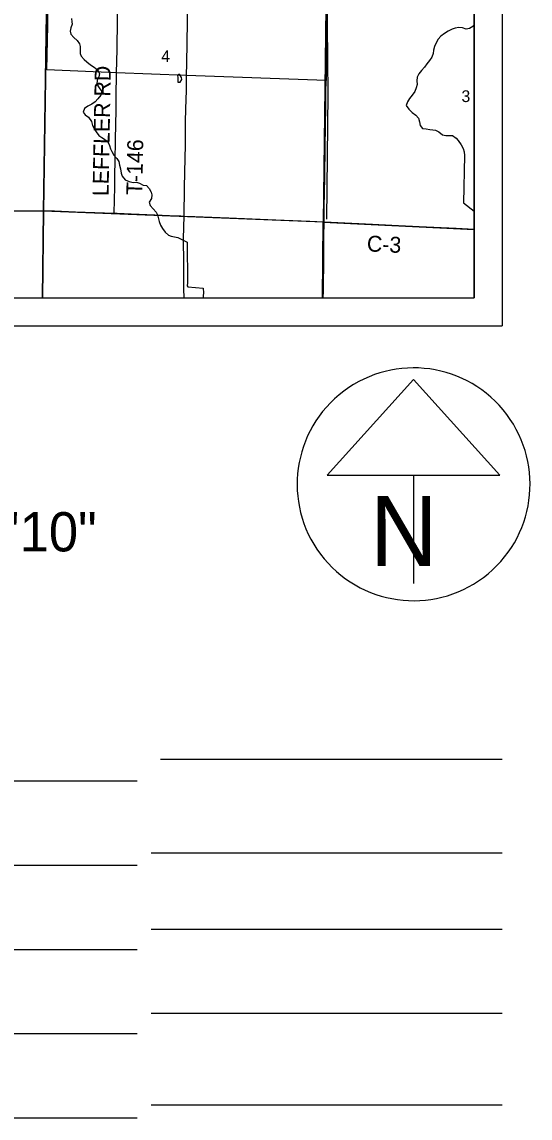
# Model space of a CAD drawing. Extents: x 0 to 39.4, y 0 to 22.
# Drawn here: x 7.289 to 9.099, y 11.177 to 15.083 of the extents above; entities that cross this region are included whole.
import ezdxf

# ---------------------------------------------------------------- set-up
doc = ezdxf.new("R2010")
doc.units = 0
for name, color, linetype in [('Default', 7, 'Continuous'), ('GM_X_Corporation', 7, 'Continuous'), ('GM_X_County_Road', 7, 'Continuous'), ('GM_X_County_Road_Text', 7, 'Continuous'), ('GM_X_Interstate_Route', 7, 'Continuous'), ('GM_X_Minor_Lake', 7, 'Continuous'), ('GM_X_Minor_River', 7, 'Continuous'), ('GM_X_Section', 7, 'Continuous'), ('GM_X_Section_Text', 7, 'Continuous'), ('GM_X_Township_Road', 7, 'Continuous'), ('GM_X_Township_Road_Text', 7, 'Continuous'), ('SH_Data', 7, 'Continuous'), ('SH_Text', 7, 'Continuous')]:
    doc.layers.add(name, color=color, linetype=linetype)

msp = doc.modelspace()

# ---------------------------------------------------------------- linework, layer by layer
at = {"layer": 'Default'}
for points in [[(8.9, 14.3437), (8.9, 15.3135), (8.3745, 15.3277), (8.3619, 14.3697)], [(6.3661, 14.1), (7.3628, 14.1), (7.3661, 14.4082), (6.3684, 14.4076)], [(7.3628, 14.1), (8.3604, 14.1), (8.3619, 14.3697), (7.3661, 14.4082)], [(8.3604, 14.1), (8.9, 14.1), (8.9, 14.3437), (8.3619, 14.3697)]]:
    msp.add_lwpolyline(points, close=True, dxfattribs=at)
at = {"layer": 'GM_X_Corporation'}
msp.add_lwpolyline([(8.3729, 14.874), (7.8752, 14.8925), (7.6264, 14.9016), (7.3784, 14.9119), (7.3814, 15.0704), (7.3845, 15.3493), (7.3532, 15.3504), (7.3553, 15.4266), (7.3626, 15.7535), (7.3656, 15.8466), (7.8594, 15.8328), (8.3606, 15.827), (8.3571, 15.626), (8.3542, 15.4855), (8.3506, 15.3268), (8.3806, 15.3258), (8.3806, 15.3081), (8.3795, 15.2552), (8.3776, 15.1713), (8.3767, 15.1247), (8.3759, 15.0687), (8.3749, 14.9972), (8.3738, 14.9443), (8.373, 14.8915)], close=True, dxfattribs=at)
at = {"layer": 'GM_X_County_Road'}
for points in [[(8.3731, 14.8735), (8.3732, 14.8909), (8.374, 14.9438), (8.3751, 14.9966), (8.3761, 15.0681), (8.3769, 15.1241), (8.3779, 15.1707), (8.3797, 15.2547), (8.3809, 15.3075), (8.3808, 15.3252)], [(8.3659, 14.3709), (8.3663, 14.4225), (8.3679, 14.529), (8.3697, 14.6398), (8.3708, 14.7075), (8.3717, 14.785), (8.3723, 14.8327), (8.3731, 14.8735)], [(6.8685, 14.4122), (6.9639, 14.4119), (7.0136, 14.4118), (7.0665, 14.4117), (7.1224, 14.4114), (7.1721, 14.4111), (7.2187, 14.4111), (7.2591, 14.411), (7.3617, 14.4103), (7.4052, 14.4094), (7.4797, 14.4067), (7.6175, 14.4016)], [(7.6175, 14.4016), (7.6288, 14.4012), (7.6784, 14.399), (7.7623, 14.3956), (7.815, 14.3929), (7.8554, 14.3914), (7.8669, 14.391)], [(7.8669, 14.391), (7.9051, 14.3895), (8.0262, 14.3847), (8.1939, 14.3782), (8.315, 14.3732), (8.3647, 14.371), (8.3659, 14.3709)], [(8.3627, 14.1), (8.3631, 14.124), (8.3647, 14.2446), (8.365, 14.3199), (8.3658, 14.3665), (8.3659, 14.3709)], [(8.3659, 14.3709), (8.464, 14.3661), (8.5385, 14.3623), (8.6533, 14.3565), (8.7309, 14.3528), (8.8365, 14.3474), (8.9, 14.3441)]]:
    msp.add_lwpolyline(points, dxfattribs=at)
at = {"layer": 'GM_X_Interstate_Route'}
msp.add_lwpolyline([(5.3699, 15.3511), (5.3635, 14.9304), (5.3615, 14.845), (5.3629, 14.7948), (5.3638, 14.6746), (5.3656, 14.4414), (5.3613, 14.1), (8.9, 14.1), (8.9, 15.3132)], dxfattribs=at)
at = {"layer": 'GM_X_Minor_Lake'}
msp.add_line((7.8443, 14.8848), (7.8447, 14.8685), dxfattribs=at)
msp.add_lwpolyline([(7.8447, 14.8685), (7.8526, 14.8683), (7.8585, 14.878), (7.8576, 14.8852), (7.8521, 14.8949), (7.8476, 14.8972), (7.8437, 14.8924), (7.8443, 14.8848)], dxfattribs=at)
at = {"layer": 'GM_X_Minor_River'}
msp.add_line((8.9, 15.0738), (8.8955, 15.067), dxfattribs=at)
for points in [[(7.8788, 15.1315), (7.8797, 15.1577), (7.8809, 15.1642), (7.8814, 15.1718), (7.8861, 15.1766), (7.8953, 15.1822), (7.909, 15.1827), (7.9318, 15.1822), (8.0514, 15.182), (8.0784, 15.1834), (8.0839, 15.1894), (8.0894, 15.1999), (8.0948, 15.2081), (8.1052, 15.2155), (8.122, 15.2187), (8.157, 15.2203), (8.2819, 15.2165), (8.3639, 15.215), (8.3791, 15.2147), (8.3767, 15.1229), (8.3765, 15.0727)], [(7.4675, 15.0829), (7.4679, 15.0755), (7.4638, 15.0621), (7.4607, 15.0497), (7.463, 15.0394), (7.4744, 15.0272), (7.4865, 15.0173), (7.4945, 15.0053), (7.4965, 14.9957), (7.4965, 14.9858), (7.4972, 14.9706), (7.4999, 14.961), (7.5112, 14.9485), (7.5208, 14.941), (7.5334, 14.9303), (7.5471, 14.9222), (7.5589, 14.9123), (7.5653, 14.8992), (7.5626, 14.8872), (7.5573, 14.8748), (7.5561, 14.8608), (7.5648, 14.8484), (7.5742, 14.8348), (7.57, 14.822), (7.5593, 14.8091), (7.5507, 14.7987), (7.5379, 14.79), (7.5244, 14.7825), (7.5116, 14.7738), (7.5074, 14.7618), (7.5146, 14.7513), (7.5261, 14.743), (7.5366, 14.7282), (7.5411, 14.7144), (7.5457, 14.7047), (7.5536, 14.6915), (7.5634, 14.6783), (7.5734, 14.6711), (7.5831, 14.6655), (7.5956, 14.6556), (7.6017, 14.6425), (7.6051, 14.6306), (7.6093, 14.6209), (7.6165, 14.6082), (7.6278, 14.5968), (7.6343, 14.5859), (7.6373, 14.5725), (7.6402, 14.5588), (7.6432, 14.5442), (7.6462, 14.5327), (7.6572, 14.5202), (7.671, 14.5148), (7.6849, 14.5109), (7.6978, 14.5113), (7.7079, 14.5083), (7.7206, 14.5006), (7.7331, 14.5002), (7.743, 14.4892), (7.7501, 14.4765), (7.7525, 14.4669), (7.7505, 14.454), (7.7429, 14.441), (7.7463, 14.4287), (7.7565, 14.417), (7.7671, 14.4045), (7.7717, 14.3949), (7.7755, 14.3818), (7.7785, 14.3722), (7.7834, 14.3592), (7.7895, 14.3472), (7.8, 14.3339), (7.8111, 14.3233), (7.8208, 14.3199), (7.8332, 14.3168), (7.8449, 14.3149), (7.8568, 14.3092), (7.8782, 14.2976)], [(7.4662, 15.0954), (7.4675, 15.0829)], [(8.3765, 15.0727), (8.379, 14.8258), (8.3739, 14.3799)], [(8.8955, 15.067), (8.8839, 15.0598), (8.8721, 15.0575), (8.8586, 15.0618), (8.8453, 15.0626), (8.8328, 15.0607), (8.8213, 15.0566), (8.807, 15.0495), (8.7943, 15.0419), (8.7818, 15.0325), (8.7716, 15.021), (8.7643, 15.0084), (8.759, 14.9953), (8.7555, 14.9825), (8.754, 14.9704), (8.7498, 14.9572), (8.7415, 14.9457), (8.7312, 14.9336), (8.7229, 14.9221), (8.7126, 14.9103), (8.7031, 14.8984), (8.6967, 14.8861), (8.6955, 14.8729), (8.697, 14.8599), (8.6939, 14.8482), (8.6886, 14.8351), (8.6798, 14.8225), (8.6703, 14.8095), (8.6627, 14.798), (8.6585, 14.7853), (8.6679, 14.7724), (8.6789, 14.7599), (8.6919, 14.7503), (8.7021, 14.7394), (8.7051, 14.7271), (8.7077, 14.7137), (8.7157, 14.7036), (8.7289, 14.7016), (8.7417, 14.6997), (8.7527, 14.6982), (8.7629, 14.6967), (8.7744, 14.691), (8.787, 14.6803), (8.7994, 14.678), (8.8131, 14.6783), (8.8233, 14.6779), (8.8359, 14.6684), (8.8434, 14.6608)], [(8.8434, 14.6608), (8.8533, 14.6454), (8.8608, 14.6319), (8.8646, 14.6196), (8.8653, 14.6067)], [(8.8653, 14.6067), (8.8621, 14.4382), (8.9, 14.4086)], [(7.8782, 14.2976), (7.8787, 14.1536), (7.8775, 14.1426), (7.8805, 14.1391), (7.9353, 14.1339)], [(7.9353, 14.1339), (7.9366, 14.1171), (7.9351, 14.1068), (7.9349, 14.1)]]:
    msp.add_lwpolyline(points, dxfattribs=at)
at = {"layer": 'GM_X_Section'}
for points in [[(6.3741, 15.3693), (7.3525, 15.3518), (7.3801, 15.3507), (7.3661, 14.4082), (6.3684, 14.4076)], [(8.348, 15.3299), (8.3745, 15.3277), (8.3619, 14.3697), (7.3661, 14.4082), (7.3801, 15.3507)]]:
    msp.add_lwpolyline(points, close=True, dxfattribs=at)
at = {"layer": 'GM_X_Township_Road'}
for points in [[(7.6266, 14.901), (7.6282, 14.985), (7.6301, 15.0905), (7.6307, 15.1526), (7.6309, 15.1836), (7.6313, 15.2165), (7.6313, 15.2248)], [(7.8755, 14.891), (7.8755, 14.8919), (7.8761, 14.9362), (7.8785, 15.0824), (7.8794, 15.1353), (7.8796, 15.1664), (7.8807, 15.2171)], [(7.6239, 14.7238), (7.6246, 14.7623), (7.6252, 14.815), (7.6266, 14.901)], [(7.8669, 14.391), (7.8686, 14.4921), (7.8695, 14.5481), (7.8714, 14.6444), (7.8725, 14.7284), (7.8736, 14.7719), (7.875, 14.8403), (7.8754, 14.8714), (7.8755, 14.891)], [(7.6228, 14.6647), (7.6238, 14.7159), (7.6239, 14.7238)], [(7.6207, 14.5573), (7.6208, 14.5673), (7.6213, 14.6045), (7.6224, 14.6446), (7.6228, 14.6647)], [(7.6175, 14.4016), (7.6178, 14.4093), (7.6188, 14.4403), (7.6201, 14.5022), (7.6207, 14.5573)], [(7.8667, 14.1), (7.8665, 14.1315), (7.8658, 14.1843), (7.8654, 14.2496), (7.865, 14.2838), (7.8651, 14.3087), (7.866, 14.3522), (7.8669, 14.3895), (7.8669, 14.391)]]:
    msp.add_lwpolyline(points, dxfattribs=at)
at = {"layer": 'SH_Data'}
for p, q in [((9, 21), (9, 14)), ((8.9, 20.9), (8.9, 14.1)), ((2.1, 14.1), (8.9, 14.1)), ((2, 14), (9, 14)), ((8.6845, 13.8091), (8.3769, 13.4678)), ((8.9921, 13.4678), (8.6845, 13.8091)), ((8.3769, 13.4678), (8.9921, 13.4678)), ((8.6845, 13.4678), (8.6845, 13.0811)), ((8.6845, 13.4353), (8.6845, 13.4353)), ((8.6845, 13.4353), (8.6845, 13.4353)), ((7.7827, 12.4553), (9, 12.4553)), ((7.7, 12.3767), (4.4937, 12.3767)), ((9, 12.1207), (7.75, 12.1207)), ((7.7, 12.0767), (3.9895, 12.0767)), ((9, 11.8491), (7.75, 11.8491)), ((7.7, 11.7767), (3.6192, 11.7767)), ((9, 11.5491), (7.75, 11.5491)), ((7.7, 11.4767), (3.3288, 11.4767)), ((9, 11.2223), (7.75, 11.2223)), ((7.7, 11.1767), (4.7452, 11.1767))]:
    msp.add_line(p, q, dxfattribs=at)
msp.add_arc((8.6845, 13.4353), 0.4148, 129.7798, 129.7633, dxfattribs=at)

# ---------------------------------------------------------------- texts
at = {"layer": 'GM_X_County_Road_Text'}
msp.add_text('C-3', height=0.05682, rotation=357.2517, dxfattribs=at).set_placement((8.517, 14.2653))
at = {"layer": 'GM_X_Section_Text'}
for s, p in [('4', (7.7855, 14.9401)), ('3', (8.8551, 14.7973))]:
    msp.add_text(s, height=0.0419, rotation=0, dxfattribs=at).set_placement(p)
at = {"layer": 'GM_X_Township_Road_Text'}
for s, rotation, p in [('LEFFLER RD', 88.9518, (7.5976, 14.4619)), ('T-146', 88.8765, (7.7179, 14.4656))]:
    msp.add_text(s, height=0.05682, rotation=rotation, dxfattribs=at).set_placement(p)
at = {"layer": 'SH_Data'}
msp.add_text('N', height=0.25, dxfattribs=at).set_placement((8.5292, 13.144))
at = {"layer": 'SH_Text'}
msp.add_text('LATITUDE:  N41°17\'00"     LONGITUDE:  W83°39\'10"', height=0.14, dxfattribs=at).set_placement((3.071, 13.1959))

doc.saveas('drawing.dxf')
